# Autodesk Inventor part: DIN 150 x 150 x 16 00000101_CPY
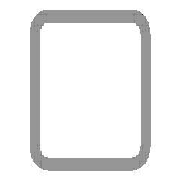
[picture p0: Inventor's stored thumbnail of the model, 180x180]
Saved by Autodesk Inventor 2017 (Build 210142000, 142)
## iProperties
Created: 2017-11
Part Number: DIN 150 x 150 x 16 00000101_CPY
Material: Steel, Mild
Description: Cold formed welded structural hollow sections of non-alloy and fine grain structural steel
Document SubType Name: Modeling
Standard: DIN
Designer: iusti
Standard Revision: 2006-07
Standards Organization: DIN
Language: en-US
Size Designation: 150 x 150 x 16
Categories: <MemberInstance><Categories><Category DisplayName="Structural Shapes" InternalName="089c4875-fa83-4c05-b084-43b9cc11f5ed" Mnemonic="GRDR"><CategoryParameter Dis
Stock Number: 150 x 150 x 16
Mass: 88044.5 g
Surface Area: 14205.2 cm^2
Volume: 11215.9 cm^3
Density: 7.85 g/cm^3
Appearance: Semi-Polished
IsCustomPart: 1
G_W: 150.000 mm
G_H: 150.000 mm
G_L: 1602.478 mm
+987C6673-447C-412A-9B24-0CD20188E66E+CUTDETAIL2: Miter 69.88 deg
+D0655DDE-97F9-4B99-A490-E36C02108510+CUTDETAIL3: Miter 45.00 deg
_CCFamilyMember: 76
_CCFamilyDisplayName: DIN EN 10219-2 (Square Hollow Section - Cold Formed) - Cold formed welded structural hollow sections of non-alloy and fine grain structural steel
_FrameMemberDoc: Frame Member File
_Version: 15.0.0
_GetPNFromCC: 1
Author: iusti
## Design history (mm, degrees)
node "Start plane"
node "End plane"
sketch "Sketch"
  geometry: L1 (-75, -27)-(-75, 27); L2 (-27, 75)-(27, 75); L3 (75, 27)-(75, -27); L4 (27, -75)-(-27, -75); L5 (-27, 59)-(27, 59); L6 (59, 27)-(59, -27); L7 (27, -59)-(-27, -59); L8 (-59, -27)-(-59, 27); L9 (0, 118.918)-(0, -118.918) reference; L10 (-118.918, 0)-(118.918, 0) reference; A1 r 48 centre (-27, -27) between (-75, -27) and (-27, -75); A2 r 48 centre (-27, 27) between (-27, 75) and (-75, 27); A3 r 48 centre (27, 27) between (75, 27) and (27, 75); A4 r 48 centre (27, -27) between (27, -75) and (75, -27); A5 r 32 centre (-27, 27) between (-27, 59) and (-59, 27); A6 r 32 centre (27, 27) between (59, 27) and (27, 59); A7 r 32 centre (27, -27) between (27, -59) and (59, -27); A8 r 32 centre (-27, -27) between (-59, -27) and (-27, -59)
  constraints: 16 end point, 16 point on circle, 8 centre point, 8 tangent, 4 parallel, 3 equal radius, 2 perpendicular, 7 other
  dimensions: "d7" = 48 radius of A1 (= G_IR); "d10" = 150 distance between parallel lines of L2 L4 (= G_H); "d11" = 150 distance between parallel lines of L1 L3 (= G_W); "d12" = 16 distance between parallel lines of L3 L6 (= G_T); "d15" = 75 distance between parallel lines of L2 L10 (= 0.5 x d10); "d16" = 75 distance between parallel lines of L9 L3 (= 0.5 x d11)
extrude "Body" new body sketch "Sketch" stored distance "d3" = 1602.4779 (= G_L); taper "d4" = 0 deg
node "Driven Length"
  sketch "Sketch3"
    geometry: L1 (0, 0)-(10, 0) reference
    constraints: 2 end point, 1 horizontal
  workplane "Work Plane3"
  sketch "Sketch4"
    geometry: L1 (-2, -27.478)-(12, -27.478) reference; L2 (-2, 1575)-(12, 1575) reference
    dimensions: "d18" = 1602.4779 distance between parallel lines of L1 L2 (derived)
workplane "Work Plane5"
split "Split2"
workplane "Work Plane6"
split "Split3"
body "Solid1"
other parameters: "G_W" = 150 [user parameter; used in 1 equation term], "G_H" = 150 [user parameter; used in 1 equation term], "G_T" = 16 [user parameter; used in 1 equation term], "G_IR" = 48 [user parameter; used in 1 equation term], "G_L" = 1602.4779 (= d18) [user parameter; used in 1 equation term], "G_OFFSET_START" = 27.4779 [user parameter; used in 1 equation term], "G_OFFSET_END" = 75 [user parameter; used in 1 equation term], "d13" = -27.4779 (= -G_OFFSET_START), "d14" = 1575 (= G_OFFSET_END + B_L), "d17" = 90 deg
